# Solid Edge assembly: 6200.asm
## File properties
Author: PARTuser1
Template: Normal.asm
Last saved by: PARTuser1
Revision: 1
Application: Solid Edge
CADENASNORM: 6200
CADENAS_NB: 6200
CADENAS_NBSYN: 6200
CADENAS_LINA: 6200
CADENAS_PSOL_MULTISOLIDPART: 0
CADENAS_Z: 8.000
CADENAS_Y0W2: 9.239
CADENAS_R0N1: 0.000
CADENAS_DOUT: 30.000
CADENAS_YI: 8.500
CADENAS_D1ICOS: 23.200
CADENAS_YE: 11.600
CADENAS_Y0I: 10.000
CADENAS_D2: 24.800
CADENAS_D1: 23.200
CADENAS_Y0E: 10.000
CADENAS_X0I: 4.500
CADENAS_BN1: 0.000
CADENAS_CE: 0.000
CADENAS_R2I: 0.200
CADENAS_RWB: 2.381
CADENAS_X0E: 4.500
CADENAS_R2E: 0.200
CADENAS_Z0W2: 3.827
CADENAS_RI: 2.381
CADENAS_X0WB: 4.500
CADENAS_BICOS: 0.000
CADENAS_HIS1: 0.000
CADENAS_RE: 2.381
CADENAS_XI: 0.000
CADENAS_RC: 0.000
CADENAS_XE: 0.000
CADENAS_HE2: 2.600
CADENAS_X0W2: 4.500
CADENAS_BOREDIAMETER: 10.000
CADENAS_RSG: 0.283
CADENAS_BI: 9.000
CADENAS_HN1: 0.000
CADENAS_HI: 3.500
CADENAS_BE: 9.000
CADENAS_R1I: 0.600
CADENAS_HH: 0.000
CADENAS_PRODUCTID: 1050010200.000
CADENAS_HE: 3.400
CADENAS_BEARINGWIDTH: 9.000
CADENAS_R1E: 0.600
CADENAS_BICOS1: 0.000
CADENAS_HICOS: 0.000
CADENAS_DKI: 17.000
CADENAS_Y0WB: 10.000
CADENAS_comment: design:dgbb1; version:5000.3; lang:it; selectedUnitParts:000000; action:download; skf2d3daction.jsp version:2008-03-06; getRequestURI:/skf/skf3dnew/skf2d3daction.jsp
CADENAS_KT: DUMMY
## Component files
6200_PART1.par
6200_PART2.par
6200_PART3.par
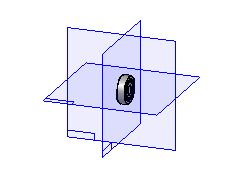
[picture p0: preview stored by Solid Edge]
